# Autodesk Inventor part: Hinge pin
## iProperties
Author: Tom Cross
Shininess: 41.0
PropertySet Name: _Private Model Information
Length Units: 11272
Angle Units: 11286
Time Units: 11279
Mass Units: 11290
Length Display Precision: 3
Angle Display Precision: 2
Compacted: True
Created: 2001-09
Part Number: Hinge pin
Document SubType Name: Modeling
Designer: Tom Cross
Control State: 0
Master: False
Checked Out: False
PropertySet Name: Design Tracking Control
Density: 0.0
Volumn: 0.0
Area: 0.0
PropertySet Name: Model Information
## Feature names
1. Extrusion1
